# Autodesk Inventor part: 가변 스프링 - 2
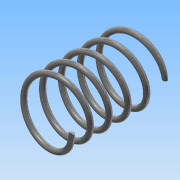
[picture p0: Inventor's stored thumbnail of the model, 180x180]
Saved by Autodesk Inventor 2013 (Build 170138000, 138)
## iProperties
Created: 2016-01
Part Number: 가변 스프링 - 2
Material: 스테인리스강
Document SubType Name: Modeling
Designer: Administrator
Mass: 8.67 g
Surface Area: 21.7147 cm^2
Volume: 1.07302 cm^3
Density: 8.08 g/cm^3
Author: Administrator
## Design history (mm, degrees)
sketch "스케치1"
  geometry: L1 (0, 0)-(11, 0); L2 (11, 0)-(11, 36.411); L3 (11, 36.411)-(0, 36.411); L4 (0, 36.411)-(0, 0); C1 r 1 at (11, 0)
  constraints: 8 end point, 2 parallel, 1 centre point, 1 coincident, 1 horizontal, 1 perpendicular
  dimensions: "d0" = 2 diameter of C1; "d2" = 22 diameter of L2 L4; "d3" = 36.4112 distance between parallel lines of L1 L3 (derived)
feature "코일1" sketch "스케치1" pitch "d4" = 10; turns "d6" = 5; dims "d5" = 36.4112 (= d3), "d7" = 0, angle "d8" = 90 deg, angle "d9" = 90 deg, "d10" = 0, "d11" = 0
feature "분할1"
node "작업 평면1"
feature "분할2"
node "솔리드1"
other parameters: "d12" = 90 deg
